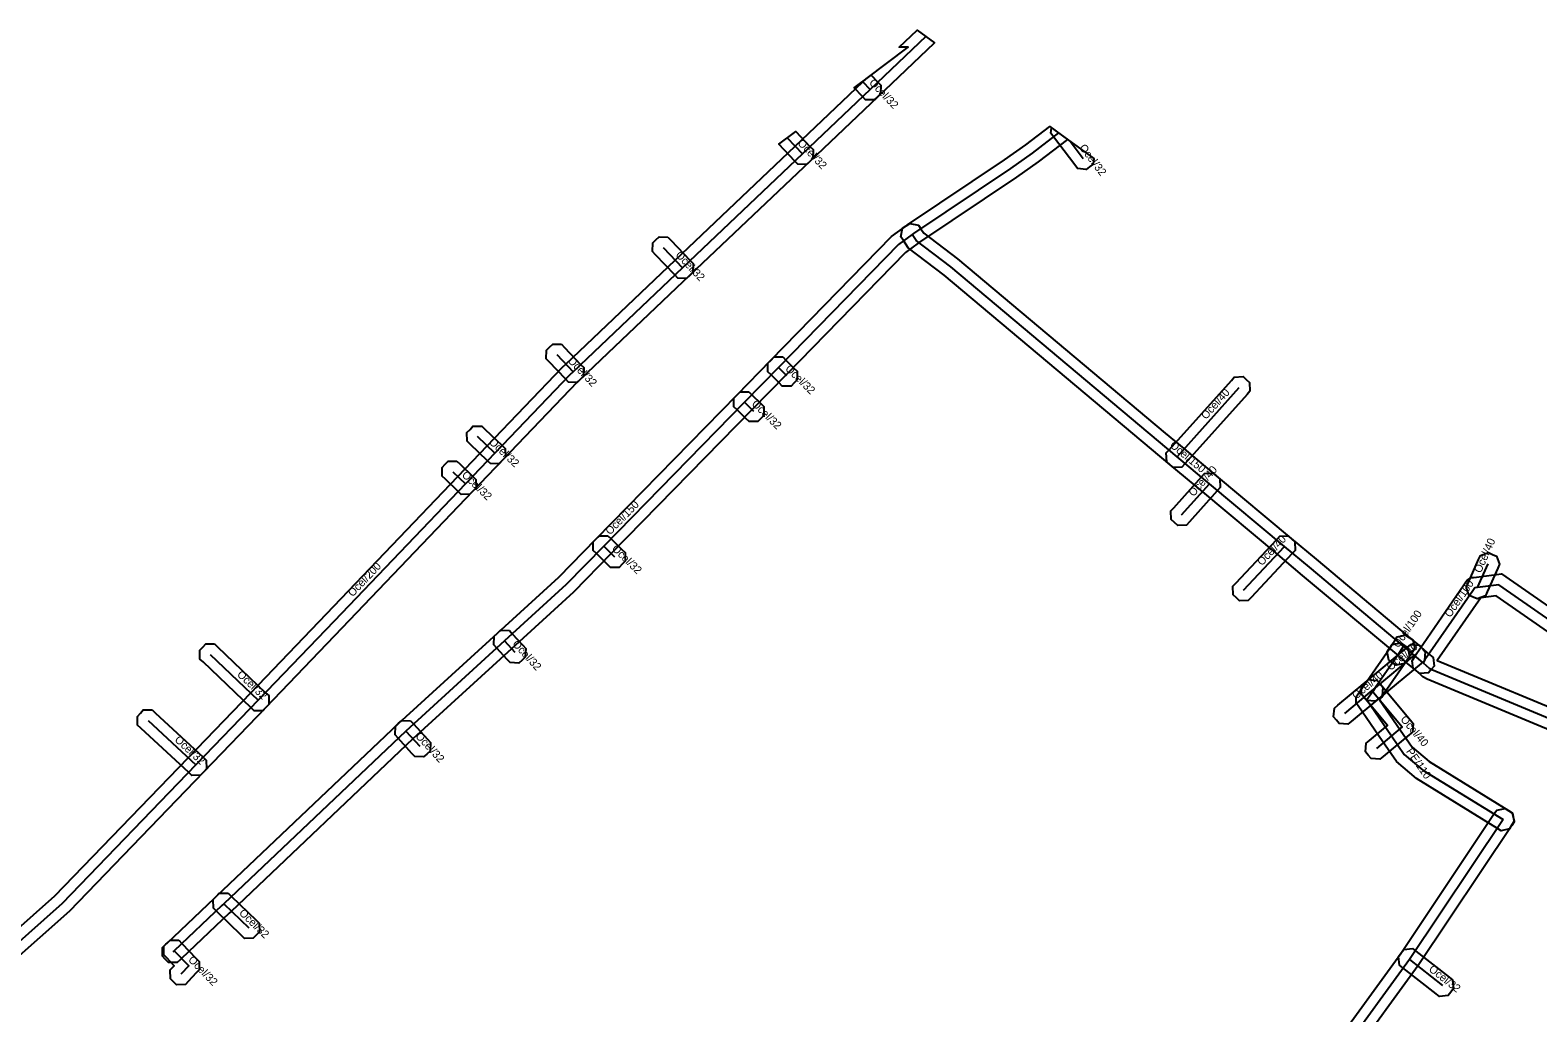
# Model space of a CAD drawing. Extents: x -600607 to -600238, y -1203924 to -1203617.
# Drawn here: x -600461.6 to -600318.4, y -1203710.4 to -1203617 of the extents above; entities that cross this region are included whole.
import ezdxf

# ---------------------------------------------------------------- set-up
doc = ezdxf.new("R2010")
doc.units = 0
for name, color, linetype in [('1', 7, 'Continuous'), ('14', 7, 'Continuous'), ('18', 7, 'Continuous'), ('20', 7, 'Continuous')]:
    doc.layers.add(name, color=color, linetype=linetype)

msp = doc.modelspace()

# ---------------------------------------------------------------- linework, layer by layer
at = {"layer": '1'}
for points in [[(-600467.41, -1203706.51), (-600459.26, -1203699.29), (-600446.59, -1203686.16), (-600440.66, -1203680.01), (-600433.46, -1203672.48), (-600420.99, -1203659.45), (-600418.19, -1203656.52), (-600411.05, -1203649.06), (-600410.73, -1203648.75), (-600400.34, -1203638.88), (-600388.94, -1203628.04), (-600382.5, -1203621.93), (-600382.2, -1203621.64), (-600378.21, -1203618.65), (-600379.05, -1203618.65), (-600377.34, -1203617.02), (-600375.69, -1203618.22), (-600375.73, -1203618.25), (-600381.12, -1203623.38), (-600387.56, -1203629.5), (-600398.96, -1203640.32), (-600409.35, -1203650.21), (-600409.65, -1203650.48), (-600416.75, -1203657.9), (-600419.55, -1203660.83), (-600432.02, -1203673.86), (-600439.22, -1203681.39), (-600445.15, -1203687.54), (-600457.88, -1203700.73), (-600466.09, -1203708.01)], [(-600314.13, -1203684.83), (-600328.89, -1203678.68), (-600329.3, -1203678.46), (-600329.94, -1203677.88), (-600330.21, -1203677.64), (-600330.31, -1203676.94), (-600330.13, -1203676.63), (-600329.95, -1203676.33), (-600325.4, -1203669.74), (-600325.21, -1203669.46), (-600325.08, -1203669.28), (-600324.71, -1203669.05), (-600324.49, -1203669.03), (-600324.21, -1203669), (-600321.82, -1203668.7), (-600308.67, -1203677.85)], [(-600309.81, -1203679.49), (-600322.34, -1203670.78), (-600323.81, -1203670.96), (-600327.93, -1203676.92), (-600313.29, -1203683.01)], [(-600337.88, -1203713.69), (-600331.4, -1203704.76), (-600322.52, -1203691.47), (-600322.29, -1203691.13), (-600321.48, -1203690.97), (-600321.13, -1203691.2), (-600320.79, -1203691.43), (-600320.63, -1203692.24), (-600320.86, -1203692.59), (-600329.76, -1203705.9), (-600336.24, -1203714.83)]]:
    msp.add_lwpolyline(points, dxfattribs=at)
for points in [[(-600382.53, -1203623.34), (-600383.34, -1203622.49), (-600381.73, -1203621.29), (-600381.09, -1203621.96), (-600380.8, -1203622.26), (-600380.82, -1203623.09), (-600381.12, -1203623.37), (-600381.42, -1203623.66), (-600382.25, -1203623.64)], [(-600367.02, -1203627.92), (-600364.75, -1203626.17), (-600363.06, -1203627.4), (-600365.84, -1203629.53), (-600367.92, -1203631), (-600377.12, -1203637.17), (-600377.24, -1203637.26), (-600378.46, -1203638.16), (-600389.8, -1203649.78), (-600393.04, -1203653.09), (-600406.41, -1203666.76), (-600409.99, -1203670.43), (-600415.88, -1203675.8), (-600425.25, -1203684.36), (-600442.53, -1203700.76), (-600442.71, -1203700.94), (-600447.23, -1203705.23), (-600447.36, -1203705.35), (-600447.66, -1203705.63), (-600448.49, -1203705.61), (-600448.78, -1203705.31), (-600449.06, -1203705.01), (-600449.04, -1203704.18), (-600448.74, -1203703.89), (-600448.61, -1203703.77), (-600444.09, -1203699.49), (-600443.91, -1203699.31), (-600426.61, -1203682.9), (-600417.22, -1203674.32), (-600411.39, -1203668.99), (-600407.83, -1203665.36), (-600394.46, -1203651.69), (-600391.24, -1203648.38), (-600379.78, -1203636.64), (-600378.42, -1203635.64), (-600378.26, -1203635.53), (-600369.06, -1203629.36)], [(-600388.97, -1203629.46), (-600390.5, -1203627.86), (-600388.89, -1203626.65), (-600387.53, -1203628.08), (-600387.24, -1203628.38), (-600387.26, -1203629.21), (-600387.56, -1203629.49), (-600387.86, -1203629.78), (-600388.69, -1203629.76)], [(-600364.65, -1203626.82), (-600364.58, -1203626.3), (-600360.56, -1203629.22), (-600360.64, -1203629.77), (-600360.96, -1203630.02), (-600361.3, -1203630.27), (-600362.11, -1203630.16), (-600362.37, -1203629.82), (-600364.4, -1203627.16)], [(-600401.03, -1203636.69), (-600400.74, -1203636.99), (-600398.92, -1203638.91), (-600398.64, -1203639.21), (-600398.66, -1203640.04), (-600398.96, -1203640.33), (-600399.26, -1203640.61), (-600400.09, -1203640.59), (-600400.38, -1203640.29), (-600402.2, -1203638.37), (-600402.48, -1203638.07), (-600402.46, -1203637.24), (-600402.16, -1203636.95), (-600401.86, -1203636.67)], [(-600329.59, -1203678.17), (-600329.91, -1203677.91), (-600330.76, -1203677.2), (-600331.78, -1203676.33), (-600340.73, -1203668.83), (-600343.09, -1203666.86), (-600350.22, -1203660.9), (-600353.3, -1203658.33), (-600355.07, -1203656.85), (-600374.77, -1203640.31), (-600378.19, -1203637.71), (-600378.66, -1203637.01), (-600378.89, -1203636.67), (-600378.73, -1203635.85), (-600378.39, -1203635.62), (-600378.05, -1203635.39), (-600377.23, -1203635.54), (-600377, -1203635.89), (-600376.71, -1203636.31), (-600373.52, -1203638.75), (-600353.79, -1203655.31), (-600352.02, -1203656.79), (-600348.94, -1203659.36), (-600341.81, -1203665.32), (-600339.45, -1203667.29), (-600330.5, -1203674.8), (-600329.48, -1203675.66), (-600328.63, -1203676.37), (-600328.31, -1203676.64), (-600328.24, -1203677.46), (-600328.5, -1203677.78), (-600328.77, -1203678.1)], [(-600411.14, -1203646.87), (-600410.85, -1203647.17), (-600409.32, -1203648.79), (-600409.03, -1203649.09), (-600409.05, -1203649.92), (-600409.35, -1203650.21), (-600409.65, -1203650.49), (-600410.48, -1203650.47), (-600410.77, -1203650.17), (-600412.31, -1203648.55), (-600412.59, -1203648.25), (-600412.57, -1203647.42), (-600412.27, -1203647.14), (-600411.97, -1203646.85)], [(-600390.11, -1203648.08), (-600389.82, -1203648.37), (-600389.05, -1203649.13), (-600388.75, -1203649.42), (-600388.75, -1203650.25), (-600389.04, -1203650.54), (-600389.33, -1203650.84), (-600390.16, -1203650.84), (-600390.45, -1203650.55), (-600391.22, -1203649.79), (-600391.52, -1203649.5), (-600391.52, -1203648.67), (-600391.23, -1203648.38), (-600390.94, -1203648.08)], [(-600353.68, -1203657.2), (-600353.4, -1203656.89), (-600347.49, -1203650.3), (-600347.22, -1203649.99), (-600346.39, -1203649.95), (-600346.08, -1203650.23), (-600345.77, -1203650.5), (-600345.73, -1203651.33), (-600346.01, -1203651.64), (-600351.92, -1203658.23), (-600352.19, -1203658.54), (-600353.02, -1203658.58), (-600353.33, -1203658.3), (-600353.64, -1203658.03)], [(-600393.34, -1203651.39), (-600393.05, -1203651.68), (-600392.21, -1203652.51), (-600391.91, -1203652.8), (-600391.91, -1203653.63), (-600392.2, -1203653.92), (-600392.49, -1203654.22), (-600393.32, -1203654.22), (-600393.61, -1203653.93), (-600394.45, -1203653.1), (-600394.75, -1203652.81), (-600394.75, -1203651.98), (-600394.46, -1203651.69), (-600394.17, -1203651.39)], [(-600417.86, -1203658.22), (-600418.16, -1203657.94), (-600419.8, -1203656.38), (-600420.1, -1203656.09), (-600420.12, -1203655.26), (-600419.83, -1203654.96), (-600419.55, -1203654.66), (-600418.72, -1203654.64), (-600418.42, -1203654.93), (-600416.78, -1203656.49), (-600416.48, -1203656.77), (-600416.46, -1203657.6), (-600416.74, -1203657.9), (-600417.03, -1203658.2)], [(-600421.07, -1203657.97), (-600420.78, -1203658.26), (-600419.58, -1203659.42), (-600419.28, -1203659.71), (-600419.26, -1203660.54), (-600419.55, -1203660.83), (-600419.84, -1203661.13), (-600420.67, -1203661.15), (-600420.96, -1203660.86), (-600422.17, -1203659.7), (-600422.46, -1203659.41), (-600422.48, -1203658.58), (-600422.19, -1203658.28), (-600421.9, -1203657.99)], [(-600353.25, -1203662.71), (-600352.97, -1203662.4), (-600350.32, -1203659.46), (-600350.05, -1203659.15), (-600349.22, -1203659.11), (-600348.91, -1203659.39), (-600348.6, -1203659.67), (-600348.56, -1203660.49), (-600348.84, -1203660.8), (-600351.49, -1203663.74), (-600351.77, -1203664.05), (-600352.59, -1203664.09), (-600352.9, -1203663.81), (-600353.21, -1203663.53)], [(-600406.72, -1203665.06), (-600406.42, -1203665.35), (-600405.39, -1203666.36), (-600405.09, -1203666.65), (-600405.09, -1203667.47), (-600405.38, -1203667.77), (-600405.67, -1203668.07), (-600406.49, -1203668.07), (-600406.79, -1203667.78), (-600407.82, -1203666.77), (-600408.12, -1203666.48), (-600408.12, -1203665.66), (-600407.83, -1203665.36), (-600407.54, -1203665.06)], [(-600347.35, -1203669.86), (-600347.07, -1203669.56), (-600343.18, -1203665.41), (-600342.9, -1203665.1), (-600342.07, -1203665.08), (-600341.77, -1203665.36), (-600341.46, -1203665.64), (-600341.44, -1203666.47), (-600341.72, -1203666.77), (-600345.61, -1203670.92), (-600345.89, -1203671.23), (-600346.72, -1203671.25), (-600347.02, -1203670.97), (-600347.33, -1203670.69)], [(-600325.18, -1203669.96), (-600325.01, -1203669.58), (-600324.01, -1203667.34), (-600323.84, -1203666.96), (-600323.07, -1203666.67), (-600322.69, -1203666.84), (-600322.31, -1203667.01), (-600322.02, -1203667.78), (-600322.19, -1203668.16), (-600323.19, -1203670.4), (-600323.36, -1203670.78), (-600324.13, -1203671.07), (-600324.51, -1203670.9), (-600324.89, -1203670.73)], [(-600444.11, -1203675.33), (-600443.81, -1203675.62), (-600439.25, -1203679.98), (-600438.95, -1203680.26), (-600438.93, -1203681.09), (-600439.22, -1203681.39), (-600439.5, -1203681.69), (-600440.33, -1203681.71), (-600440.63, -1203681.42), (-600445.19, -1203677.06), (-600445.49, -1203676.78), (-600445.51, -1203675.95), (-600445.22, -1203675.65), (-600444.94, -1203675.35)], [(-600416.09, -1203674.08), (-600415.81, -1203674.38), (-600414.82, -1203675.46), (-600414.54, -1203675.77), (-600414.58, -1203676.6), (-600414.88, -1203676.88), (-600415.19, -1203677.16), (-600416.02, -1203677.12), (-600416.3, -1203676.82), (-600417.29, -1203675.74), (-600417.57, -1203675.43), (-600417.53, -1203674.6), (-600417.23, -1203674.32), (-600416.92, -1203674.04)], [(-600330.57, -1203676.54), (-600330.81, -1203676.88), (-600333.01, -1203680.08), (-600333.24, -1203680.43), (-600333.42, -1203680.67), (-600331.47, -1203683.51), (-600330.32, -1203685.17), (-600328.72, -1203686.53), (-600321.17, -1203691.18), (-600320.81, -1203691.4), (-600320.62, -1203692.2), (-600320.84, -1203692.55), (-600321.06, -1203692.91), (-600321.86, -1203693.1), (-600322.21, -1203692.88), (-600329.9, -1203688.15), (-600331.82, -1203686.53), (-600333.11, -1203684.65), (-600335.45, -1203681.24), (-600335.63, -1203680.98), (-600335.63, -1203680.36), (-600335.45, -1203680.1), (-600334.9, -1203679.29), (-600334.67, -1203678.96), (-600332.45, -1203675.74), (-600332.22, -1203675.4), (-600331.4, -1203675.25), (-600331.06, -1203675.49), (-600330.72, -1203675.72)], [(-600329.16, -1203676.93), (-600329.48, -1203677.2), (-600333.5, -1203680.54), (-600333.82, -1203680.8), (-600334.64, -1203680.73), (-600334.91, -1203680.41), (-600335.17, -1203680.09), (-600335.1, -1203679.27), (-600334.78, -1203679), (-600330.76, -1203675.66), (-600330.44, -1203675.4), (-600329.62, -1203675.47), (-600329.35, -1203675.79), (-600329.09, -1203676.11)], [(-600330.07, -1203675.76), (-600330.3, -1203676.11), (-600330.52, -1203676.45), (-600330.8, -1203676.87), (-600331.04, -1203677.22), (-600331.85, -1203677.37), (-600332.19, -1203677.14), (-600332.54, -1203676.9), (-600332.69, -1203676.09), (-600332.46, -1203675.75), (-600332.19, -1203675.35), (-600331.98, -1203675.03), (-600331.76, -1203674.68), (-600330.95, -1203674.5), (-600330.6, -1203674.73), (-600330.25, -1203674.95)], [(-600333.18, -1203680.27), (-600333.5, -1203680.54), (-600336.11, -1203682.72), (-600336.43, -1203682.98), (-600337.25, -1203682.91), (-600337.52, -1203682.59), (-600337.78, -1203682.27), (-600337.71, -1203681.45), (-600337.39, -1203681.18), (-600334.78, -1203679), (-600334.46, -1203678.74), (-600333.64, -1203678.81), (-600333.37, -1203679.13), (-600333.11, -1203679.45)], [(-600333.64, -1203678.81), (-600333.37, -1203679.13), (-600330.49, -1203682.59), (-600330.23, -1203682.91), (-600330.3, -1203683.73), (-600330.62, -1203684), (-600333.08, -1203686.05), (-600333.4, -1203686.31), (-600334.22, -1203686.24), (-600334.49, -1203685.92), (-600334.75, -1203685.6), (-600334.68, -1203684.78), (-600334.36, -1203684.51), (-600332.67, -1203683.1), (-600334.91, -1203680.41), (-600335.17, -1203680.09), (-600335.1, -1203679.27), (-600334.78, -1203679), (-600334.46, -1203678.74)], [(-600450.04, -1203681.6), (-600449.74, -1203681.88), (-600445.19, -1203686.12), (-600444.89, -1203686.4), (-600444.86, -1203687.23), (-600445.14, -1203687.53), (-600445.42, -1203687.83), (-600446.25, -1203687.86), (-600446.55, -1203687.58), (-600451.1, -1203683.34), (-600451.41, -1203683.06), (-600451.43, -1203682.23), (-600451.15, -1203681.93), (-600450.87, -1203681.62)], [(-600425.47, -1203682.65), (-600425.19, -1203682.95), (-600423.87, -1203684.39), (-600423.59, -1203684.7), (-600423.63, -1203685.53), (-600423.93, -1203685.81), (-600424.24, -1203686.09), (-600425.07, -1203686.05), (-600425.35, -1203685.75), (-600426.67, -1203684.31), (-600426.95, -1203684), (-600426.91, -1203683.17), (-600426.61, -1203682.89), (-600426.3, -1203682.61)], [(-600442.82, -1203699.03), (-600442.52, -1203699.31), (-600440.16, -1203701.6), (-600439.86, -1203701.89), (-600439.84, -1203702.72), (-600440.13, -1203703.01), (-600440.42, -1203703.31), (-600441.25, -1203703.33), (-600441.55, -1203703.04), (-600443.91, -1203700.75), (-600444.21, -1203700.46), (-600444.22, -1203699.63), (-600443.94, -1203699.34), (-600443.65, -1203699.04)], [(-600447.49, -1203703.51), (-600447.2, -1203703.81), (-600445.83, -1203705.23), (-600445.56, -1203705.52), (-600445.55, -1203706.32), (-600445.83, -1203706.61), (-600446.59, -1203707.41), (-600446.87, -1203707.71), (-600447.7, -1203707.73), (-600448, -1203707.45), (-600448.3, -1203707.16), (-600448.32, -1203706.33), (-600448.04, -1203706.03), (-600447.94, -1203705.93), (-600448.64, -1203705.19), (-600448.93, -1203704.89), (-600448.92, -1203704.06), (-600448.62, -1203703.78), (-600448.32, -1203703.49)], [(-600330.29, -1203704.29), (-600329.96, -1203704.54), (-600326.81, -1203707.02), (-600326.49, -1203707.28), (-600326.39, -1203708.1), (-600326.64, -1203708.43), (-600326.9, -1203708.75), (-600327.72, -1203708.85), (-600328.05, -1203708.6), (-600331.2, -1203706.12), (-600331.52, -1203705.86), (-600331.62, -1203705.04), (-600331.37, -1203704.71), (-600331.11, -1203704.39)]]:
    msp.add_lwpolyline(points, close=True, dxfattribs=at)
at = {"layer": '14'}
for points in [[(-600376.52, -1203617.62), (-600381.81, -1203622.65), (-600388.25, -1203628.77), (-600399.65, -1203639.6), (-600410.04, -1203649.48), (-600410.35, -1203649.77), (-600417.47, -1203657.21), (-600420.27, -1203660.14), (-600432.74, -1203673.17), (-600439.94, -1203680.7), (-600445.87, -1203686.85), (-600458.57, -1203700.01), (-600466.75, -1203707.26), (-600469.55, -1203709.74), (-600472.59, -1203712.26), (-600475.67, -1203714.29), (-600481.14, -1203718.36), (-600486.68, -1203722.48)], [(-600382.53, -1203621.89), (-600381.81, -1203622.65)], [(-600363.91, -1203626.79), (-600366.43, -1203628.72), (-600368.49, -1203630.18), (-600377.69, -1203636.35), (-600377.83, -1203636.45), (-600379.12, -1203637.4), (-600390.52, -1203649.08), (-600393.75, -1203652.39), (-600407.12, -1203666.06), (-600410.69, -1203669.71), (-600416.55, -1203675.06), (-600425.93, -1203683.63), (-600443.22, -1203700.03), (-600443.4, -1203700.21), (-600447.92, -1203704.5), (-600448.05, -1203704.62)], [(-600389.69, -1203627.25), (-600388.25, -1203628.77)], [(-600362.82, -1203627.58), (-600361.57, -1203629.22)], [(-600329.27, -1203677.14), (-600330.12, -1203676.43), (-600331.14, -1203675.57), (-600340.09, -1203668.06), (-600342.45, -1203666.09), (-600349.58, -1203660.13), (-600352.66, -1203657.56), (-600354.43, -1203656.08), (-600374.14, -1203639.53), (-600377.45, -1203637.01), (-600377.83, -1203636.45)], [(-600401.47, -1203637.68), (-600399.65, -1203639.6)], [(-600411.58, -1203647.86), (-600410.04, -1203649.48)], [(-600390.52, -1203649.08), (-600389.75, -1203649.84)], [(-600352.66, -1203657.56), (-600346.75, -1203650.97)], [(-600393.75, -1203652.39), (-600392.91, -1203653.22)], [(-600421.47, -1203658.98), (-600420.27, -1203660.14)], [(-600352.23, -1203663.07), (-600349.58, -1203660.13)], [(-600407.12, -1203666.06), (-600406.09, -1203667.07)], [(-600346.34, -1203670.24), (-600342.45, -1203666.09)], [(-600324.1, -1203669.99), (-600323.1, -1203667.75)], [(-600309.24, -1203678.67), (-600322.08, -1203669.74), (-600324.1, -1203669.99), (-600324.38, -1203670.02), (-600324.57, -1203670.3), (-600329.11, -1203676.87), (-600329.27, -1203677.14), (-600328.72, -1203677.64), (-600328.46, -1203677.78), (-600313.71, -1203683.92)], [(-600416.55, -1203675.06), (-600415.56, -1203676.14)], [(-600444.5, -1203676.34), (-600439.94, -1203680.7)], [(-600331.63, -1203676.31), (-600333.84, -1203679.52), (-600334.07, -1203679.86), (-600334.63, -1203680.67), (-600332.29, -1203684.08), (-600331.07, -1203685.85), (-600329.31, -1203687.34), (-600321.69, -1203692.03)], [(-600330.12, -1203676.43), (-600333.84, -1203679.52), (-600334.14, -1203679.77)], [(-600331.14, -1203675.57), (-600331.35, -1203675.9), (-600331.63, -1203676.31)], [(-600334.14, -1203679.77), (-600336.75, -1203681.95)], [(-600334.14, -1203679.77), (-600331.26, -1203683.23), (-600333.72, -1203685.28)], [(-600425.93, -1203683.63), (-600424.61, -1203685.07)], [(-600321.69, -1203692.03), (-600330.58, -1203705.33), (-600337.06, -1203714.26), (-600337.47, -1203714.88), (-600341.61, -1203721.03), (-600343.93, -1203724.48), (-600344.29, -1203725.01), (-600352.8, -1203737.19), (-600355.42, -1203740.94), (-600356.36, -1203742.04), (-600356.56, -1203742.28), (-600357.37, -1203743.06), (-600358.82, -1203744.14), (-600359.04, -1203744.31), (-600359.16, -1203744.4), (-600365.08, -1203752.77), (-600365.18, -1203752.95), (-600368.57, -1203759.1), (-600375.05, -1203770.85), (-600375.18, -1203771.08)], [(-600447.92, -1203704.5), (-600446.55, -1203705.92), (-600447.31, -1203706.72)]]:
    msp.add_lwpolyline(points, dxfattribs=at)
at = {"layer": '18'}
for points in [[(-600417.47, -1203657.21), (-600419.11, -1203655.65)], [(-600450.42, -1203682.61), (-600445.87, -1203686.85)], [(-600443.22, -1203700.03), (-600440.85, -1203702.32)], [(-600330.58, -1203705.33), (-600327.43, -1203707.81)]]:
    msp.add_lwpolyline(points, dxfattribs=at)

# ---------------------------------------------------------------- texts
at = {"layer": '20'}
for s, rotation, p in [('Ocel/32', 313.573, (-600381.97, -1203622.07)), ('Ocel/32', 313.6028, (-600388.77, -1203627.81)), ('Ocel/32', 307.2457, (-600361.99, -1203628.2)), ('Ocel/32', 313.4684, (-600400.36, -1203638.44)), ('Ocel/32', 313.5498, (-600410.61, -1203648.47)), ('Ocel/32', 315.3745, (-600389.94, -1203649.26)), ('Ocel/32', 315.3431, (-600393.13, -1203652.6)), ('Ocel/40', 48.1138, (-600349.9, -1203654.07)), ('Ocel/32', 316.4321, (-600418.09, -1203656.23)), ('Ocel/150', 320.099, (-600353.41, -1203656.57)), ('Ocel/32', 315.971, (-600420.67, -1203659.36)), ('Ocel/40', 47.9697, (-600351.1, -1203661.4)), ('Ocel/150', 45.6357, (-600406.52, -1203665.04)), ('Ocel/40', 46.8522, (-600344.59, -1203667.97)), ('Ocel/40', 65.9427, (-600323.8, -1203668.67)), ('Ocel/32', 315.5617, (-600406.41, -1203666.36)), ('Ocel/200', 46.2581, (-600430.98, -1203670.92)), ('Ocel/100', 55.3548, (-600326.7, -1203672.89)), ('Ocel/100', 55.6698, (-600331.61, -1203675.78)), ('Ocel/32', 312.5104, (-600415.86, -1203675.4)), ('Ocel/40', 39.7146, (-600332.37, -1203677.93)), ('Ocel/32', 316.2844, (-600442.02, -1203678.32)), ('Ocel/40', 39.8703, (-600335.65, -1203680.66)), ('Ocel/40', 309.773, (-600331.48, -1203682.53)), ('Ocel/32', 312.5104, (-600425.07, -1203684.15)), ('Ocel/32', 317.0198, (-600447.95, -1203684.53)), ('PE/110', 304.5772, (-600330.93, -1203685.56)), ('Ocel/32', 315.9485, (-600441.83, -1203700.98)), ('Ocel/32', 313.892, (-600446.66, -1203705.41)), ('Ocel/32', 321.7866, (-600328.81, -1203706.37))]:
    msp.add_text(s, height=0.75, rotation=rotation, dxfattribs=at).set_placement(p)

doc.saveas('drawing.dxf')
